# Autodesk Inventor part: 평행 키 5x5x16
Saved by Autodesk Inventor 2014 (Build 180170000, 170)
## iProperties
Created: 2026-07
Part Number: 평행 키 5x5x16
Material: 강철, 연강
Document SubType Name: Modeling
Designer: dg
Density: 7.86 g/cm^3
Appearance: 강철
Mass: 2.88679 g
Surface Area: 3.19722 cm^2
Volume: 0.367276 cm^3
Author: jhkim
Description: 키 및 해당 키홈
Creation Date: 2026-07-02
Sending System: Autodesk Inventor 2027
Preprocessor: ST-DEVELOPER v20.1
Author: dg
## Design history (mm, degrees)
node "평행 키 5x5x161"
body "Solid1"
node "기준1"
